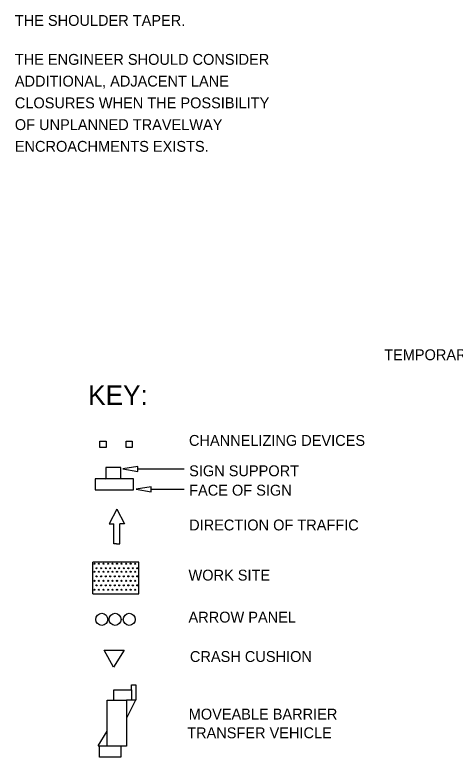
# Model space of a CAD drawing. Extents: x 1531.5 to 1538.6, y 1529.6 to 1539.6.
# Drawn here: x 1531.471 to 1533.901, y 1531.741 to 1535.839 of the extents above; entities that cross this region are included whole.
import ezdxf

# ---------------------------------------------------------------- set-up
doc = ezdxf.new("R2010")
doc.units = 0
for name, color, linetype in [('DETL-DIMS', 7, 'Continuous'), ('DETL-LINE', 7, 'Continuous'), ('DETL-NOTE', 7, 'Continuous'), ('DETL-TITL', 7, 'Continuous'), ('USER-BORD', 7, 'Continuous')]:
    doc.layers.add(name, color=color, linetype=linetype)

# ---------------------------------------------------------------- blocks, each defined once
blk = doc.blocks.new('CD1')
at = {"layer": 'USER-BORD'}
blk.add_lwpolyline([(0, 0.0312), (0.0312, 0.0312), (0.0312, 0), (0, 0)], close=True, dxfattribs=at)
blk = doc.blocks.new('DIR2')
at = {"layer": 'USER-BORD'}
for p, q in [((0, 0.0012), (-0.0342, -0.0477)), ((0, 0.0012), (0.0342, -0.0477)), ((-0.0342, -0.0477), (-0.0132, -0.0477)), ((-0.0132, -0.1133), (-0.0132, -0.0477)), ((0.0342, -0.0477), (0.0132, -0.0477)), ((0.0132, -0.1133), (0.0132, -0.0477)), ((-0.0011, -0.1133), (-0.0132, -0.1133)), ((-0.0011, -0.1133), (0.0011, -0.1133)), ((0.0011, -0.1133), (0.0132, -0.1133))]:
    blk.add_line(p, q, dxfattribs=at)
blk = doc.blocks.new('SIGN13')
at = {"layer": 'USER-BORD'}
for points in [[(-0.0134, 0.0182), (0.011, 0.0189), (0.011, 0.0371), (-0.0134, 0.0371)], [(-0.0314, 0.0182), (-0.0314, 0), (0.032, 0), (0.032, 0.0182)]]:
    blk.add_lwpolyline(points, close=True, dxfattribs=at)

msp = doc.modelspace()

# ---------------------------------------------------------------- linework, layer by layer
at = {"layer": 'DETL-DIMS'}
for p, q in [((1532.1493, 1533.3327), (1532.4063, 1533.3327)), ((1532.2236, 1533.2201), (1532.4063, 1533.2201))]:
    msp.add_line(p, q, dxfattribs=at)
for points in [[(1532.1493, 1533.3189), (1532.1493, 1533.3465), (1532.0662, 1533.3327)], [(1532.2236, 1533.2063), (1532.2236, 1533.2339), (1532.1406, 1533.2201)]]:
    msp.add_lwpolyline(points, close=True, dxfattribs=at)
at = {"layer": 'DETL-LINE'}
for p, q in [((1532.1549, 1532.8178), (1531.9009, 1532.8178)), ((1532.1549, 1532.8178), (1531.9009, 1532.8178)), ((1532.1549, 1532.8178), (1531.9009, 1532.8178)), ((1532.1549, 1532.8178), (1531.9009, 1532.8178)), ((1531.9009, 1532.6437), (1531.9009, 1532.8177)), ((1531.9009, 1532.6438), (1531.9009, 1532.8177)), ((1531.9095, 1532.8089), (1531.9095, 1532.8089)), ((1531.9103, 1532.8089), (1531.9103, 1532.8089)), ((1531.9351, 1532.8089), (1531.9351, 1532.8089)), ((1531.9351, 1532.8089), (1531.9351, 1532.8089)), ((1531.9599, 1532.8089), (1531.9599, 1532.8089)), ((1531.9607, 1532.8089), (1531.9607, 1532.8089)), ((1531.9847, 1532.8089), (1531.9847, 1532.8089)), ((1531.9855, 1532.8089), (1531.9855, 1532.8089)), ((1532.0095, 1532.8089), (1532.0095, 1532.8089)), ((1532.0103, 1532.8089), (1532.0103, 1532.8089)), ((1532.0351, 1532.8089), (1532.0351, 1532.8089)), ((1532.0351, 1532.8089), (1532.0351, 1532.8089)), ((1532.0599, 1532.8089), (1532.0599, 1532.8089)), ((1532.0599, 1532.8089), (1532.0599, 1532.8089)), ((1532.0847, 1532.8089), (1532.0847, 1532.8089)), ((1532.0855, 1532.8089), (1532.0855, 1532.8089)), ((1532.1095, 1532.8089), (1532.1095, 1532.8089)), ((1532.1103, 1532.8089), (1532.1103, 1532.8089)), ((1532.1351, 1532.8089), (1532.1351, 1532.8089)), ((1532.1351, 1532.8089), (1532.1351, 1532.8089)), ((1532.1549, 1532.6438), (1532.1549, 1532.8178)), ((1532.1549, 1532.6438), (1532.1549, 1532.8178)), ((1532.1549, 1532.6438), (1532.1549, 1532.8178)), ((1532.1549, 1532.6438), (1532.1549, 1532.8178)), ((1531.9095, 1532.7651), (1531.9095, 1532.7651)), ((1531.9103, 1532.7651), (1531.9103, 1532.7651)), ((1531.9223, 1532.7841), (1531.9223, 1532.7841)), ((1531.9223, 1532.7841), (1531.9223, 1532.7841)), ((1531.9351, 1532.7651), (1531.9351, 1532.7651)), ((1531.9351, 1532.7651), (1531.9351, 1532.7651)), ((1531.9471, 1532.7841), (1531.9471, 1532.7841)), ((1531.9471, 1532.7841), (1531.9471, 1532.7841)), ((1531.9599, 1532.7651), (1531.9599, 1532.7651)), ((1531.9607, 1532.7651), (1531.9607, 1532.7651)), ((1531.9727, 1532.7841), (1531.9727, 1532.7841)), ((1531.9727, 1532.7841), (1531.9727, 1532.7841)), ((1531.9847, 1532.7651), (1531.9847, 1532.7651)), ((1531.9855, 1532.7651), (1531.9855, 1532.7651)), ((1531.9975, 1532.7841), (1531.9975, 1532.7841)), ((1531.9975, 1532.7841), (1531.9975, 1532.7841)), ((1532.0095, 1532.7651), (1532.0095, 1532.7651)), ((1532.0103, 1532.7651), (1532.0103, 1532.7651)), ((1532.0223, 1532.7841), (1532.0223, 1532.7841)), ((1532.0223, 1532.7841), (1532.0223, 1532.7841)), ((1532.0351, 1532.7651), (1532.0351, 1532.7651)), ((1532.0351, 1532.7651), (1532.0351, 1532.7651)), ((1532.0471, 1532.7841), (1532.0471, 1532.7841)), ((1532.0471, 1532.7841), (1532.0471, 1532.7841)), ((1532.0599, 1532.7651), (1532.0599, 1532.7651)), ((1532.0599, 1532.7651), (1532.0599, 1532.7651)), ((1532.0719, 1532.7841), (1532.0719, 1532.7841)), ((1532.0719, 1532.7841), (1532.0719, 1532.7841)), ((1532.0847, 1532.7651), (1532.0847, 1532.7651)), ((1532.0855, 1532.7651), (1532.0855, 1532.7651)), ((1532.0975, 1532.7841), (1532.0975, 1532.7841)), ((1532.0975, 1532.7841), (1532.0975, 1532.7841)), ((1532.1095, 1532.7651), (1532.1095, 1532.7651)), ((1532.1103, 1532.7651), (1532.1103, 1532.7651)), ((1532.1223, 1532.7841), (1532.1223, 1532.7841)), ((1532.1223, 1532.7841), (1532.1223, 1532.7841)), ((1532.1351, 1532.7651), (1532.1351, 1532.7651)), ((1532.1351, 1532.7651), (1532.1351, 1532.7651)), ((1532.1471, 1532.7841), (1532.1471, 1532.7841)), ((1532.1471, 1532.7841), (1532.1471, 1532.7841)), ((1531.9095, 1532.7147), (1531.9095, 1532.7147)), ((1531.9103, 1532.7147), (1531.9103, 1532.7147)), ((1531.9223, 1532.7395), (1531.9223, 1532.7395)), ((1531.9351, 1532.7147), (1531.9351, 1532.7147)), ((1531.9351, 1532.7147), (1531.9351, 1532.7147)), ((1531.9471, 1532.7395), (1531.9471, 1532.7395)), ((1531.9599, 1532.7147), (1531.9599, 1532.7147)), ((1531.9607, 1532.7147), (1531.9607, 1532.7147)), ((1531.9727, 1532.7395), (1531.9727, 1532.7395)), ((1531.9847, 1532.7147), (1531.9847, 1532.7147)), ((1531.9855, 1532.7147), (1531.9855, 1532.7147)), ((1531.9975, 1532.7395), (1531.9975, 1532.7395)), ((1532.0095, 1532.7147), (1532.0095, 1532.7147)), ((1532.0103, 1532.7147), (1532.0103, 1532.7147)), ((1532.0223, 1532.7395), (1532.0223, 1532.7395)), ((1532.0351, 1532.7147), (1532.0351, 1532.7147)), ((1532.0351, 1532.7147), (1532.0351, 1532.7147)), ((1532.0471, 1532.7395), (1532.0471, 1532.7395)), ((1532.0599, 1532.7147), (1532.0599, 1532.7147)), ((1532.0599, 1532.7147), (1532.0599, 1532.7147)), ((1532.0719, 1532.7395), (1532.0719, 1532.7395)), ((1532.0847, 1532.7147), (1532.0847, 1532.7147)), ((1532.0855, 1532.7147), (1532.0855, 1532.7147)), ((1532.0975, 1532.7395), (1532.0975, 1532.7395)), ((1532.1095, 1532.7147), (1532.1095, 1532.7147)), ((1532.1103, 1532.7147), (1532.1103, 1532.7147)), ((1532.1223, 1532.7395), (1532.1223, 1532.7395)), ((1532.1351, 1532.7147), (1532.1351, 1532.7147)), ((1532.1351, 1532.7147), (1532.1351, 1532.7147)), ((1532.1471, 1532.7395), (1532.1471, 1532.7395)), ((1531.9223, 1532.6899), (1531.9223, 1532.6899)), ((1531.9223, 1532.6899), (1531.9223, 1532.6899)), ((1531.9471, 1532.6899), (1531.9471, 1532.6899)), ((1531.9471, 1532.6899), (1531.9471, 1532.6899)), ((1531.9727, 1532.6899), (1531.9727, 1532.6899)), ((1531.9727, 1532.6899), (1531.9727, 1532.6899)), ((1531.9975, 1532.6899), (1531.9975, 1532.6899)), ((1531.9975, 1532.6899), (1531.9975, 1532.6899)), ((1532.0223, 1532.6899), (1532.0223, 1532.6899)), ((1532.0223, 1532.6899), (1532.0223, 1532.6899)), ((1532.0471, 1532.6899), (1532.0471, 1532.6899)), ((1532.0471, 1532.6899), (1532.0471, 1532.6899)), ((1532.0719, 1532.6899), (1532.0719, 1532.6899)), ((1532.0719, 1532.6899), (1532.0719, 1532.6899)), ((1532.0975, 1532.6899), (1532.0975, 1532.6899)), ((1532.0975, 1532.6899), (1532.0975, 1532.6899)), ((1532.1223, 1532.6899), (1532.1223, 1532.6899)), ((1532.1223, 1532.6899), (1532.1223, 1532.6899)), ((1532.1471, 1532.6899), (1532.1471, 1532.6899)), ((1532.1471, 1532.6899), (1532.1471, 1532.6899)), ((1531.9009, 1532.6437), (1532.1549, 1532.6437)), ((1531.9095, 1532.6655), (1531.9095, 1532.6655)), ((1531.9103, 1532.6655), (1531.9103, 1532.6655)), ((1531.9351, 1532.6655), (1531.9351, 1532.6655)), ((1531.9351, 1532.6655), (1531.9351, 1532.6655)), ((1531.9599, 1532.6655), (1531.9599, 1532.6655)), ((1531.9607, 1532.6655), (1531.9607, 1532.6655)), ((1531.9847, 1532.6655), (1531.9847, 1532.6655)), ((1531.9855, 1532.6655), (1531.9855, 1532.6655)), ((1532.0095, 1532.6655), (1532.0095, 1532.6655)), ((1532.0103, 1532.6655), (1532.0103, 1532.6655)), ((1532.0351, 1532.6655), (1532.0351, 1532.6655)), ((1532.0351, 1532.6655), (1532.0351, 1532.6655)), ((1532.0599, 1532.6655), (1532.0599, 1532.6655)), ((1532.0599, 1532.6655), (1532.0599, 1532.6655)), ((1532.0847, 1532.6655), (1532.0847, 1532.6655)), ((1532.0855, 1532.6655), (1532.0855, 1532.6655)), ((1532.1095, 1532.6655), (1532.1095, 1532.6655)), ((1532.1103, 1532.6655), (1532.1103, 1532.6655)), ((1532.1351, 1532.6655), (1532.1351, 1532.6655)), ((1532.1351, 1532.6655), (1532.1351, 1532.6655)), ((1531.9646, 1532.3319), (1532.0747, 1532.3319)), ((1532.0148, 1532.2379), (1531.9646, 1532.3319)), ((1532.0747, 1532.3319), (1532.0148, 1532.2379)), ((1532.1157, 1532.1411), (1532.138, 1532.1411)), ((1532.1157, 1532.1119), (1532.1157, 1532.1411)), ((1532.138, 1532.1411), (1532.138, 1532.0563)), ((1532.0164, 1532.0563), (1532.0164, 1532.1122)), ((1532.0164, 1532.1122), (1532.1157, 1532.1122)), ((1532.1157, 1532.1122), (1532.1157, 1532.0563)), ((1531.9809, 1531.8938), (1531.9809, 1532.0563)), ((1531.9809, 1532.0563), (1532.0875, 1532.0563)), ((1532.1229, 1532.0563), (1532.0874, 1532.0563)), ((1532.0875, 1532.0563), (1532.0875, 1531.8024)), ((1532.1373, 1532.0557), (1532.0875, 1531.957)), ((1532.138, 1532.0563), (1532.12, 1532.0563)), ((1531.9809, 1531.8024), (1531.9809, 1531.8938)), ((1531.9809, 1531.8938), (1531.9809, 1531.8938)), ((1531.9311, 1531.8037), (1531.9809, 1531.8845)), ((1531.9311, 1531.8037), (1531.9809, 1531.8037)), ((1531.9378, 1531.7415), (1531.9378, 1531.8037)), ((1532.0875, 1531.8028), (1531.9809, 1531.8028)), ((1532.0554, 1531.8024), (1532.0554, 1531.7415)), ((1532.0554, 1531.7415), (1531.9378, 1531.7415))]:
    msp.add_line(p, q, dxfattribs=at)
for centre, radius in [((1531.9102, 1532.8088), 0.00291), ((1531.935, 1532.8088), 0.00291), ((1531.9606, 1532.8088), 0.00291), ((1531.9854, 1532.8088), 0.00291), ((1532.0102, 1532.8088), 0.00291), ((1532.035, 1532.8088), 0.00291), ((1532.0598, 1532.8088), 0.00291), ((1532.0854, 1532.8088), 0.00291), ((1532.1102, 1532.8088), 0.00291), ((1532.135, 1532.8088), 0.00291), ((1531.9102, 1532.765), 0.00291), ((1531.9222, 1532.784), 0.00291), ((1531.935, 1532.765), 0.00291), ((1531.947, 1532.784), 0.00291), ((1531.9606, 1532.765), 0.00291), ((1531.9726, 1532.784), 0.00291), ((1531.9854, 1532.765), 0.00291), ((1531.9974, 1532.784), 0.00291), ((1532.0102, 1532.765), 0.00291), ((1532.0222, 1532.784), 0.00291), ((1532.035, 1532.765), 0.00291), ((1532.047, 1532.784), 0.00291), ((1532.0598, 1532.765), 0.00291), ((1532.0718, 1532.784), 0.00291), ((1532.0854, 1532.765), 0.00291), ((1532.0974, 1532.784), 0.00291), ((1532.1102, 1532.765), 0.00291), ((1532.1222, 1532.784), 0.00291), ((1532.135, 1532.765), 0.00291), ((1532.147, 1532.784), 0.00291), ((1531.9102, 1532.7146), 0.00291), ((1531.9222, 1532.7394), 0.00291), ((1531.935, 1532.7146), 0.00291), ((1531.947, 1532.7394), 0.00291), ((1531.9606, 1532.7146), 0.00291), ((1531.9726, 1532.7394), 0.00291), ((1531.9854, 1532.7146), 0.00291), ((1531.9974, 1532.7394), 0.00291), ((1532.0102, 1532.7146), 0.00291), ((1532.0222, 1532.7394), 0.00291), ((1532.035, 1532.7146), 0.00291), ((1532.047, 1532.7394), 0.00291), ((1532.0598, 1532.7146), 0.00291), ((1532.0718, 1532.7394), 0.00291), ((1532.0854, 1532.7146), 0.00291), ((1532.0974, 1532.7394), 0.00291), ((1532.1102, 1532.7146), 0.00291), ((1532.1222, 1532.7394), 0.00291), ((1532.135, 1532.7146), 0.00291), ((1532.147, 1532.7394), 0.00291), ((1531.9222, 1532.6898), 0.00291), ((1531.947, 1532.6898), 0.00291), ((1531.9726, 1532.6898), 0.00291), ((1531.9974, 1532.6898), 0.00291), ((1532.0222, 1532.6898), 0.00291), ((1532.047, 1532.6898), 0.00291), ((1532.0718, 1532.6898), 0.00291), ((1532.0974, 1532.6898), 0.00291), ((1532.1222, 1532.6898), 0.00291), ((1532.147, 1532.6898), 0.00291), ((1531.9102, 1532.6654), 0.00291), ((1531.935, 1532.6654), 0.00291), ((1531.9606, 1532.6654), 0.00291), ((1531.9854, 1532.6654), 0.00291), ((1532.0102, 1532.6654), 0.00291), ((1532.035, 1532.6654), 0.00291), ((1532.0598, 1532.6654), 0.00291), ((1532.0854, 1532.6654), 0.00291), ((1532.1102, 1532.6654), 0.00291), ((1532.135, 1532.6654), 0.00291), ((1531.9507, 1532.502), 0.0333), ((1532.0241, 1532.502), 0.0333), ((1532.1026, 1532.502), 0.0333)]:
    msp.add_circle(centre, radius, dxfattribs=at)

# ---------------------------------------------------------------- block references
for name, p, xscale, yscale in [('CD1', (1531.9396, 1533.451), 1.109417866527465, 1.109417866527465), ('CD1', (1532.0846, 1533.451), 1.109417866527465, 1.109417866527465), ('SIGN13', (1532.0186, 1533.2169), 3.324138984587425, 3.324138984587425), ('DIR2', (1532.0336, 1533.108), 1.2465521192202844, 1.6620694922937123)]:
    msp.add_blockref(name, p, dxfattribs=dict(at, xscale=xscale, yscale=yscale))

# ---------------------------------------------------------------- texts
at = {"layer": 'DETL-NOTE'}
for s, p in [('THE SHOULDER TAPER.', (1531.4709, 1535.7777)), ('THE ENGINEER SHOULD CONSIDER', (1531.4709, 1535.5627)), ('ADDITIONAL, ADJACENT LANE', (1531.4709, 1535.4427)), ('CLOSURES WHEN THE POSSIBILITY', (1531.4709, 1535.3227)), ('OF UNPLANNED TRAVELWAY', (1531.4709, 1535.2027)), ('ENCROACHMENTS EXISTS.', (1531.4709, 1535.0827)), ('TEMPORARY STRIPING (TYP.)', (1533.5093, 1533.9325)), ('CHANNELIZING DEVICES', (1532.432, 1533.4597)), ('SIGN SUPPORT', (1532.433, 1533.292)), ('FACE OF SIGN', (1532.433, 1533.1849)), ('DIRECTION OF TRAFFIC', (1532.4328, 1532.9929)), ('WORK SITE', (1532.4295, 1532.7161)), ('ARROW PANEL', (1532.4295, 1532.4843)), ('CRASH CUSHION', (1532.4372, 1532.2669)), ('MOVEABLE BARRIER', (1532.4305, 1531.9491)), ('TRANSFER VEHICLE', (1532.4221, 1531.8458))]:
    msp.add_text(s, height=0.06, dxfattribs=at).set_placement(p)
at = {"layer": 'DETL-TITL'}
msp.add_text('KEY:', height=0.108, dxfattribs=at).set_placement((1531.8755, 1533.6857))

doc.saveas('drawing.dxf')
